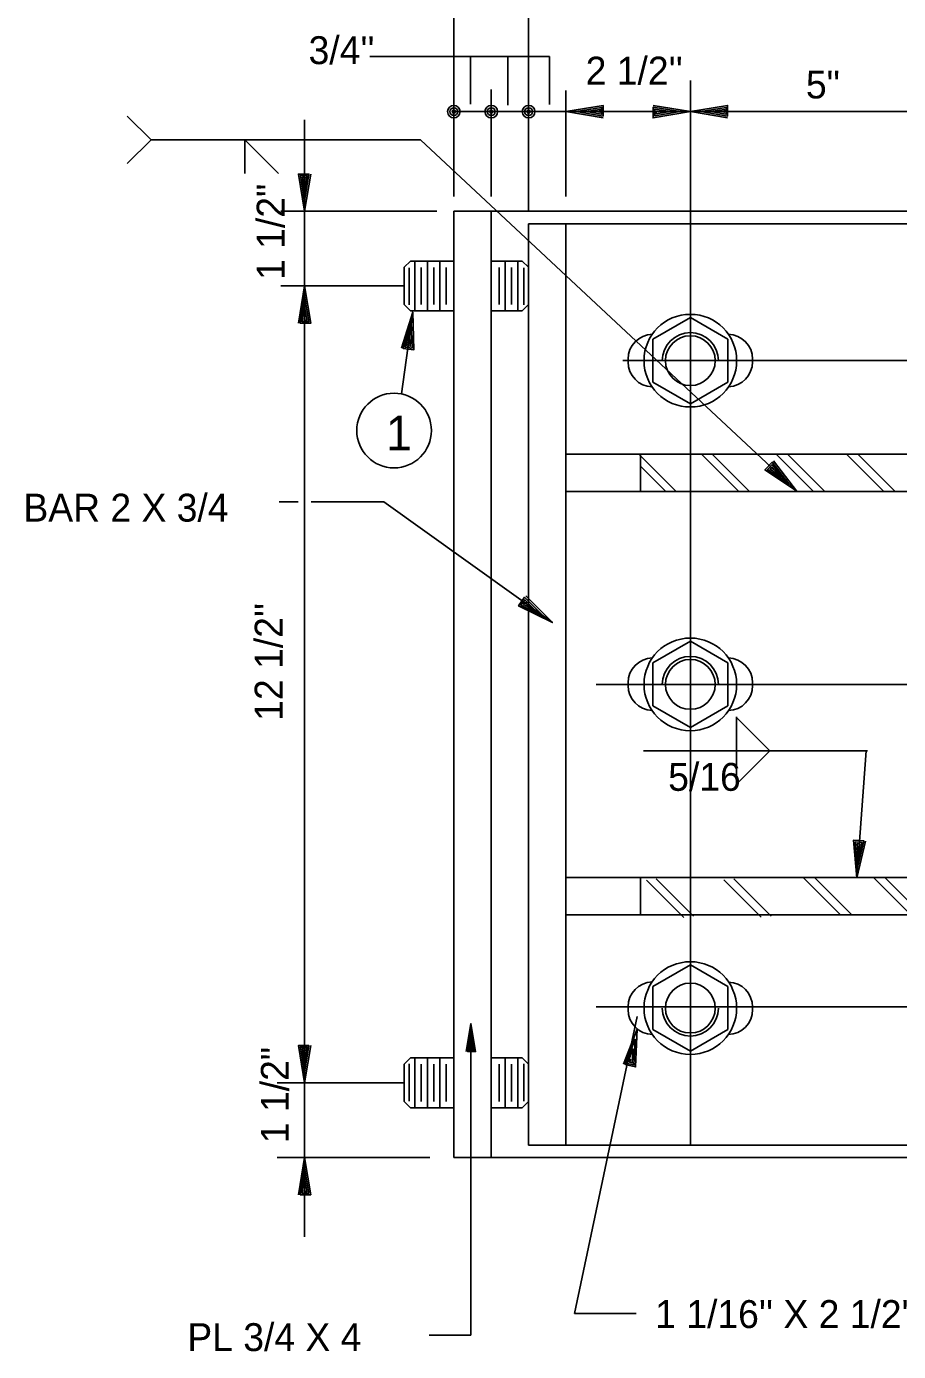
# Model space of a CAD drawing. Extents: x 0.1 to 13.5, y 0.1 to 9.5.
# Drawn here: x 6.965 to 8.425, y 1.554 to 3.771 of the extents above; entities that cross this region are included whole.
import ezdxf

# ---------------------------------------------------------------- set-up
doc = ezdxf.new("R2010")
doc.units = 0
for name, color, linetype in [('Level 2', 7, 'Continuous'), ('Level 25', 7, 'Continuous'), ('Level 3', 7, 'Continuous'), ('Level 4', 7, 'Continuous'), ('Level 50', 7, 'Continuous'), ('Level 6', 7, 'Continuous')]:
    doc.layers.add(name, color=color, linetype=linetype)

msp = doc.modelspace()

# ---------------------------------------------------------------- linework, layer by layer
at = {"layer": 'Level 2'}
for p, q in [((8.0766, 3.6807), (8.0766, 1.8993)), ((7.4308, 3.4618), (7.4308, 3.6148)), ((7.6807, 3.6285), (7.7433, 3.6285)), ((7.7433, 3.6285), (7.8058, 3.6285)), ((7.8058, 3.6285), (7.8683, 3.6285)), ((7.8683, 3.6285), (8.0766, 3.6285)), ((8.0766, 3.6285), (8.4933, 3.6285)), ((7.4308, 3.3368), (7.4308, 3.4618)), ((7.6807, 3.4618), (8.4933, 3.4618)), ((7.6807, 2.6701), (7.6807, 3.4618)), ((7.7433, 3.4618), (7.7433, 2.6701)), ((7.8058, 3.441), (8.4933, 3.441)), ((7.8058, 3.441), (7.8058, 3.2118)), ((7.8683, 3.441), (7.8683, 2.6701)), ((7.6078, 3.3785), (7.5974, 3.3681)), ((7.6078, 3.3785), (7.6807, 3.3785)), ((7.6156, 3.3785), (7.6156, 3.2948)), ((7.6365, 3.3785), (7.6365, 3.2948)), ((7.6573, 3.3785), (7.6573, 3.2948)), ((7.7433, 3.3785), (7.7953, 3.3785)), ((7.7667, 3.3785), (7.7667, 3.2948)), ((7.7876, 3.3785), (7.7876, 3.2948)), ((7.7953, 3.3785), (7.8058, 3.3681)), ((7.5974, 3.3681), (7.5974, 3.3056)), ((7.6056, 3.3674), (7.6056, 3.3052)), ((7.626, 3.3679), (7.626, 3.3057)), ((7.6469, 3.3679), (7.6469, 3.3057)), ((7.6678, 3.3679), (7.6678, 3.3057)), ((7.7563, 3.3679), (7.7563, 3.3057)), ((7.7771, 3.3679), (7.7771, 3.3057)), ((7.7976, 3.3674), (7.7976, 3.3052)), ((7.8058, 3.3681), (7.8058, 3.3056)), ((7.4308, 2.0035), (7.4308, 3.3368)), ((7.5974, 3.3056), (7.6078, 3.2951)), ((7.7953, 3.2951), (7.8058, 3.3056)), ((7.6078, 3.2951), (7.6807, 3.2951)), ((7.7433, 3.2951), (7.7953, 3.2951)), ((8.0766, 3.2841), (8.0138, 3.2478)), ((8.0766, 3.2841), (8.1393, 3.2479)), ((8.0138, 3.1758), (8.0138, 3.2478)), ((8.1393, 3.1758), (8.1393, 3.2479)), ((7.8058, 3.2118), (7.8058, 2.6701)), ((7.9634, 3.2118), (9.0554, 3.2118)), ((7.9724, 3.2096), (7.9724, 3.2144)), ((8.1807, 3.2099), (8.1808, 3.2144)), ((8.0766, 3.1395), (8.0138, 3.1758)), ((8.0766, 3.1395), (8.1393, 3.1758)), ((7.8683, 3.0556), (8.4933, 3.0556)), ((7.9933, 3.0556), (7.9933, 2.9931)), ((7.8683, 2.9931), (8.4933, 2.9931)), ((8.0766, 2.7424), (8.0139, 2.7062)), ((8.0766, 2.7424), (8.1393, 2.7062)), ((8.0139, 2.6341), (8.0139, 2.7062)), ((8.1393, 2.6341), (8.1393, 2.7062)), ((7.6807, 2.6701), (7.6807, 1.8785)), ((7.7433, 1.8785), (7.7433, 2.6701)), ((7.8058, 2.1304), (7.8058, 2.6701)), ((7.8683, 1.8993), (7.8683, 2.6701)), ((7.9725, 2.6683), (7.9724, 2.6727)), ((8.1808, 2.668), (8.1808, 2.6727)), ((8.0766, 2.5979), (8.0139, 2.6341)), ((8.0766, 2.5979), (8.1393, 2.6341)), ((7.8683, 2.3472), (8.4933, 2.3472)), ((7.9933, 2.2847), (7.9933, 2.3472)), ((7.8683, 2.2847), (8.4933, 2.2847)), ((8.0766, 2.2007), (8.0138, 2.1645)), ((8.0766, 2.2007), (8.1393, 2.1645)), ((8.0138, 2.1645), (8.0138, 2.0924)), ((8.1393, 2.1645), (8.1393, 2.0924)), ((7.8058, 1.8993), (7.8058, 2.1304)), ((7.9191, 2.1304), (8.4447, 2.1304)), ((7.9724, 2.1306), (7.9724, 2.1259)), ((8.1807, 2.1304), (8.1808, 2.1259)), ((8.0766, 2.0562), (8.0138, 2.0924)), ((8.0766, 2.0562), (8.1393, 2.0924)), ((7.5974, 2.0347), (7.6078, 2.0451)), ((7.6078, 2.0451), (7.6807, 2.0451)), ((7.6156, 1.9618), (7.6156, 2.0455)), ((7.6365, 1.9618), (7.6365, 2.0455)), ((7.6573, 1.9618), (7.6573, 2.0455)), ((7.7433, 2.0451), (7.7953, 2.0451)), ((7.7667, 1.9618), (7.7667, 2.0455)), ((7.7876, 1.9618), (7.7876, 2.0455)), ((7.7953, 2.0451), (7.8058, 2.0347)), ((7.5974, 1.9722), (7.5974, 2.0347)), ((7.6056, 1.9729), (7.6056, 2.0351)), ((7.626, 1.9724), (7.626, 2.0346)), ((7.6469, 1.9724), (7.6469, 2.0346)), ((7.6678, 1.9724), (7.6678, 2.0346)), ((7.7563, 1.9724), (7.7563, 2.0346)), ((7.7771, 1.9724), (7.7771, 2.0346)), ((7.7976, 1.9729), (7.7976, 2.0351)), ((7.8058, 1.9722), (7.8058, 2.0347)), ((7.4308, 1.8785), (7.4308, 2.0035)), ((7.6078, 1.9618), (7.5974, 1.9722)), ((7.6078, 1.9618), (7.6807, 1.9618)), ((7.7433, 1.9618), (7.7953, 1.9618)), ((7.7953, 1.9618), (7.8058, 1.9722)), ((7.8058, 1.8993), (8.4933, 1.8993)), ((7.4308, 1.7456), (7.4308, 1.8785)), ((7.6807, 1.8785), (8.4933, 1.8785))]:
    msp.add_line(p, q, dxfattribs=at)
for points in [[(8.0527, 2.9931), (7.9902, 3.0556)], [(8.1576, 2.9931), (8.0951, 3.0556)], [(8.1758, 2.9931), (8.1133, 3.0556)], [(8.2826, 2.993), (8.2201, 3.0556)], [(8.3015, 2.9931), (8.239, 3.0556)], [(8.4005, 2.993), (8.338, 3.0556)], [(8.4193, 2.993), (8.3568, 3.0556)], [(8.0354, 2.993), (7.9933, 3.0352)], [(8.0659, 2.2799), (8.0034, 2.3424)], [(8.0819, 2.2823), (8.0194, 2.3448)], [(8.195, 2.2807), (8.1325, 2.3432)], [(8.2117, 2.2823), (8.1492, 2.3448)], [(8.3281, 2.2847), (8.2655, 2.3472)], [(8.3469, 2.2847), (8.2844, 2.3472)], [(8.4459, 2.2847), (8.3834, 2.3472)], [(8.4648, 2.2847), (8.4023, 2.3472)]]:
    msp.add_lwpolyline(points, dxfattribs=at)
for centre, radius in [((8.0766, 3.2118), 0.0775), ((8.0766, 3.2118), 0.0417), ((8.0766, 2.6701), 0.0775), ((8.0766, 2.6701), 0.0417), ((8.0766, 2.1285), 0.0775), ((8.0766, 2.1285), 0.0417)]:
    msp.add_circle(centre, radius, dxfattribs=at)
for centre, radius, start, end in [((8.0141, 3.2144), 0.0417, 91.5523, 180), ((8.0766, 3.2118), 0.0469, 0, 180), ((8.1391, 3.2144), 0.0417, 0, 88.5352), ((8.0141, 3.2096), 0.0417, 180, 268.0433), ((8.139, 3.2099), 0.0417, 272.3111, 0), ((8.014, 2.6727), 0.0417, 91.4648, 180), ((8.0766, 2.6701), 0.0469, 360, 180), ((8.1391, 2.6727), 0.0417, 0, 88.4477), ((8.0141, 2.6683), 0.0417, 180, 267.6889), ((8.1391, 2.668), 0.0417, 271.9567, 0), ((8.0141, 2.1306), 0.0417, 91.9567, 180), ((8.139, 2.1304), 0.0417, 0, 87.6889), ((8.0141, 2.1259), 0.0417, 180, 268.4477), ((8.0766, 2.1285), 0.0469, 180, 360), ((8.1391, 2.1259), 0.0417, 271.4648, 0)]:
    msp.add_arc(centre, radius, start, end, dxfattribs=at)
at = {"layer": 'Level 25'}
for p, q in [((7.9191, 2.6701), (9.0634, 2.6701)), ((8.3734, 2.5587), (7.9983, 2.5587)), ((8.1538, 2.5593), (8.1538, 2.5031)), ((8.1538, 2.5031), (8.2096, 2.5589))]:
    msp.add_line(p, q, dxfattribs=at)
at = {"layer": 'Level 3'}
for p, q in [((7.6807, 3.4864), (7.6807, 3.8259)), ((7.8058, 3.4618), (7.8058, 3.8312)), ((7.54, 3.7206), (7.841, 3.7206)), ((7.7084, 3.6412), (7.7084, 3.7206)), ((7.7713, 3.6393), (7.7713, 3.7206)), ((7.841, 3.6402), (7.841, 3.7206)), ((7.7433, 3.4864), (7.7433, 3.6654)), ((7.8683, 3.4864), (7.8683, 3.6641)), ((7.6246, 3.5812), (8.2541, 2.9939)), ((7.6524, 3.4618), (7.3909, 3.4618)), ((7.5974, 3.3368), (7.3909, 3.3368)), ((7.593, 3.1562), (7.6117, 3.2928)), ((7.6117, 3.2928), (7.6117, 3.2928)), ((7.6094, 3.2757), (7.6094, 3.2757)), ((8.2415, 3.0057), (8.2415, 3.0057)), ((8.2541, 2.9939), (8.2541, 2.9939)), ((7.388, 2.9756), (7.4198, 2.9756)), ((7.4415, 2.9756), (7.5634, 2.9756)), ((7.8456, 2.7736), (7.5634, 2.9756)), ((8.371, 2.5587), (8.3552, 2.3465)), ((7.9877, 2.1141), (7.8827, 1.6176)), ((7.7092, 2.1026), (7.7092, 1.5812)), ((7.7092, 2.1026), (7.7092, 2.1026)), ((7.7092, 2.0896), (7.7092, 2.0896)), ((7.9877, 2.0932), (7.9877, 2.0932)), ((7.9841, 2.0763), (7.9841, 2.0763)), ((7.5974, 2.0035), (7.3849, 2.0035)), ((7.6406, 1.8785), (7.3849, 1.8785)), ((7.8827, 1.6176), (7.986, 1.6176)), ((7.6392, 1.5812), (7.7092, 1.5812))]:
    msp.add_line(p, q, dxfattribs=at)
for points in [[(7.593, 3.2325), (7.6117, 3.2928), (7.6135, 3.2297), (7.596, 3.2321), (7.6094, 3.2757), (7.6106, 3.2328), (7.5993, 3.2343), (7.6071, 3.2592), (7.6076, 3.2359), (7.603, 3.2365), (7.6048, 3.242)], [(8.2156, 3.044), (8.2541, 2.9939), (8.2015, 3.0289), (8.2136, 3.0418), (8.2415, 3.0057), (8.2057, 3.0295), (8.2135, 3.0378), (8.2293, 3.0171), (8.21, 3.0301), (8.2131, 3.0335), (8.2166, 3.0289)], [(7.7015, 2.0558), (7.7092, 2.1026), (7.717, 2.0558), (7.7037, 2.0558), (7.7092, 2.0896), (7.7145, 2.0578), (7.706, 2.0578), (7.7092, 2.0771), (7.712, 2.0598), (7.7085, 2.0598), (7.7092, 2.0641)], [(7.9646, 2.0344), (7.9877, 2.0932), (7.9849, 2.0301), (7.9676, 2.0338), (7.9841, 2.0763), (7.9822, 2.0334), (7.9711, 2.0357), (7.9806, 2.06), (7.9794, 2.0367), (7.9749, 2.0377), (7.977, 2.043)]]:
    msp.add_lwpolyline(points, dxfattribs=at)
msp.add_circle((7.5806, 3.0949), 0.0625, dxfattribs=at)
at = {"layer": 'Level 4'}
for p, q in [((7.1736, 3.5812), (7.1338, 3.6211)), ((7.1736, 3.5812), (7.1338, 3.5415)), ((7.6246, 3.5812), (7.1736, 3.5812)), ((7.3308, 3.5812), (7.3308, 3.525)), ((7.3308, 3.5812), (7.3868, 3.5252)), ((8.1538, 2.5593), (8.1538, 2.6156)), ((8.1538, 2.6148), (8.2096, 2.5589))]:
    msp.add_line(p, q, dxfattribs=at)
at = {"layer": 'Level 50'}
for p, q in [((7.8683, 3.6285), (7.8683, 3.6285)), ((7.8856, 3.6285), (7.8856, 3.6285)), ((8.0593, 3.6285), (8.0593, 3.6285)), ((8.0766, 3.6285), (8.0766, 3.6285)), ((8.0766, 3.6285), (8.0766, 3.6285)), ((8.0939, 3.6285), (8.0939, 3.6285)), ((7.4308, 3.4791), (7.4308, 3.4791)), ((7.4308, 3.4618), (7.4308, 3.4618)), ((7.4308, 3.3368), (7.4308, 3.3368)), ((7.4308, 3.3368), (7.4308, 3.3368)), ((7.4308, 3.3195), (7.4308, 3.3195)), ((7.4308, 3.3195), (7.4308, 3.3195)), ((7.8315, 2.7837), (7.8315, 2.7837)), ((7.8456, 2.7736), (7.8456, 2.7736)), ((8.3565, 2.3638), (8.3565, 2.3638)), ((8.3552, 2.3465), (8.3552, 2.3465)), ((7.4308, 2.0208), (7.4308, 2.0208)), ((7.4308, 2.0035), (7.4308, 2.0035)), ((7.4308, 1.8785), (7.4308, 1.8785)), ((7.4308, 1.8611), (7.4308, 1.8611))]:
    msp.add_line(p, q, dxfattribs=at)
for points in [[(7.9306, 3.6181), (7.8683, 3.6285), (7.9306, 3.6388), (7.9306, 3.6211), (7.8856, 3.6285), (7.9279, 3.6355), (7.9279, 3.6241), (7.9023, 3.6285), (7.9253, 3.6321), (7.9253, 3.6275), (7.9196, 3.6285)], [(8.0143, 3.6388), (8.0766, 3.6285), (8.0143, 3.6181), (8.0143, 3.6358), (8.0593, 3.6285), (8.0169, 3.6215), (8.0169, 3.6328), (8.0426, 3.6285), (8.0196, 3.6248), (8.0196, 3.6295), (8.0253, 3.6285)], [(8.1389, 3.6181), (8.0766, 3.6285), (8.1389, 3.6388), (8.1389, 3.6211), (8.0939, 3.6285), (8.1363, 3.6355), (8.1363, 3.6241), (8.1106, 3.6285), (8.1336, 3.6321), (8.1336, 3.6275), (8.1279, 3.6285)], [(7.4411, 3.5241), (7.4308, 3.4618), (7.4204, 3.5241), (7.4381, 3.5241), (7.4308, 3.4791), (7.4238, 3.5215), (7.4351, 3.5215), (7.4308, 3.4958), (7.4271, 3.5188), (7.4318, 3.5188), (7.4308, 3.5131)], [(7.4204, 3.2745), (7.4308, 3.3368), (7.4411, 3.2745), (7.4234, 3.2745), (7.4308, 3.3195), (7.4378, 3.2771), (7.4264, 3.2771), (7.4308, 3.3028), (7.4344, 3.2798), (7.4298, 3.2798), (7.4308, 3.2855)], [(7.4204, 3.2745), (7.4308, 3.3368), (7.4411, 3.2745), (7.4234, 3.2745), (7.4308, 3.3195), (7.4378, 3.2771), (7.4264, 3.2771), (7.4308, 3.3028), (7.4344, 3.2798), (7.4298, 3.2798), (7.4308, 3.2855)], [(7.8009, 2.8183), (7.8456, 2.7736), (7.7889, 2.8014), (7.7992, 2.8158), (7.8315, 2.7837), (7.793, 2.8026), (7.7996, 2.8118), (7.8179, 2.7934), (7.7971, 2.8038), (7.7998, 2.8076), (7.8039, 2.8034)], [(8.3701, 2.4079), (8.3552, 2.3465), (8.3495, 2.4094), (8.3672, 2.4081), (8.3565, 2.3638), (8.3527, 2.4065), (8.364, 2.4056), (8.3577, 2.3804), (8.3558, 2.4036), (8.3604, 2.4032), (8.359, 2.3977)], [(7.4411, 2.0658), (7.4308, 2.0035), (7.4204, 2.0658), (7.4381, 2.0658), (7.4308, 2.0208), (7.4238, 2.0631), (7.4351, 2.0631), (7.4308, 2.0375), (7.4271, 2.0605), (7.4318, 2.0605), (7.4308, 2.0548)], [(7.4204, 1.8161), (7.4308, 1.8785), (7.4411, 1.8161), (7.4234, 1.8161), (7.4308, 1.8611), (7.4378, 1.8188), (7.4264, 1.8188), (7.4308, 1.8445), (7.4344, 1.8215), (7.4298, 1.8215), (7.4308, 1.8271)]]:
    msp.add_lwpolyline(points, dxfattribs=at)
at = {"layer": 'Level 6'}
for centre, radius in [((7.6807, 3.6285), 0.0105), ((7.7433, 3.6285), 0.0105), ((7.8058, 3.6285), 0.0105), ((7.6807, 3.6285), 0.00659), ((7.6807, 3.6285), 0.00264), ((7.7433, 3.6285), 0.00659), ((7.7433, 3.6285), 0.00264), ((7.8058, 3.6285), 0.00659), ((7.8058, 3.6285), 0.00264)]:
    msp.add_circle(centre, radius, dxfattribs=at)

# ---------------------------------------------------------------- texts
at = {"layer": 'Level 3'}
for s, height, p in [("3/4''", 0.04667, (7.4374, 3.708)), ("2 1/2''", 0.04667, (7.9014, 3.6738)), ('5"', 0.04667, (8.2701, 3.6506)), ('1', 0.0583, (7.567, 3.0615)), ('BAR 2 X 3/4', 0.046667, (6.96, 2.9425)), ('5/16', 0.04667, (8.0395, 2.492)), ("1 1/16'' X 2 1/2'' SLOTTED HOLE", 0.046667, (8.0178, 1.5931)), ('PL 3/4 X 4', 0.04667, (7.2344, 1.5545))]:
    msp.add_text(s, height=height, dxfattribs=at).set_placement(p)
for s, p in [('1 1/2"', (7.3972, 3.3469)), ("12 1/2''", (7.3939, 2.6092)), ('1 1/2"', (7.4043, 1.9025))]:
    msp.add_text(s, height=0.04667, rotation=90, dxfattribs=at).set_placement(p)

doc.saveas('drawing.dxf')
